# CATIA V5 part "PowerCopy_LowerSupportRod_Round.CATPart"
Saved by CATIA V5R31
Part number: LowerSupportRod_Round
Bounding box of the stored display mesh (mm): x -6.954 to 16.954, y -6.954 to 16.954, z -20.502 to 120.502
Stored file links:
  C:\Users\patol451\OneDrive - Linköpings universitet\Nuvarande kurser\Exjobb\LampCATIA\PowerCopy_LowerSupportRod_Round.CATPart
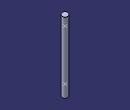
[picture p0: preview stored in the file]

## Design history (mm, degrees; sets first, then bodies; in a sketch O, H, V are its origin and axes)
Parameters
  extraLength_OneSide = 20 mm
  diameter = 10 mm
Set1 "References"
  Point1 "LowerPoint": (0, 0, 0)
  Point2 "UpperPoint": (10, 10, 100)
Set2 "Placement"
  Point3 "PlacementPoint": (0, 0, 0), relative to Point1
Set3 "Output"
  Point4 "OutputPoint1": (0, 0, 0), relative to Point2
Set4 "Geo1"
  Line1: type PtPt, FirstPoint Point1, SecondPoint Point2
  Plane1: type Normal, Curve Line1, Ratio 0
  Plane2: type Offset, RefPlane Plane1, Offset 20 {= extraLength_OneSide}, reversed
  Plane3: type OffsetPt, RefPlane Plane1, RefPoint Point2
  Plane4: type Offset, RefPlane Plane3, Offset 20 {= extraLength_OneSide}
  Project1: ToProject Point1, Support Plane2
  Project2: ToProject Point2, Support Plane4
  Line2: type PtPt, FirstPoint Project1, SecondPoint Project2
  Circle1: type CtrRad, Start 0, End 180, Center Project1, Support Plane2, Radius 5 {= diameter /2}, FirstDirection (-0.7071, 0.7071, 0)
Body1 (main body)
  Rib1: profile Circle1, centre curve Line2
